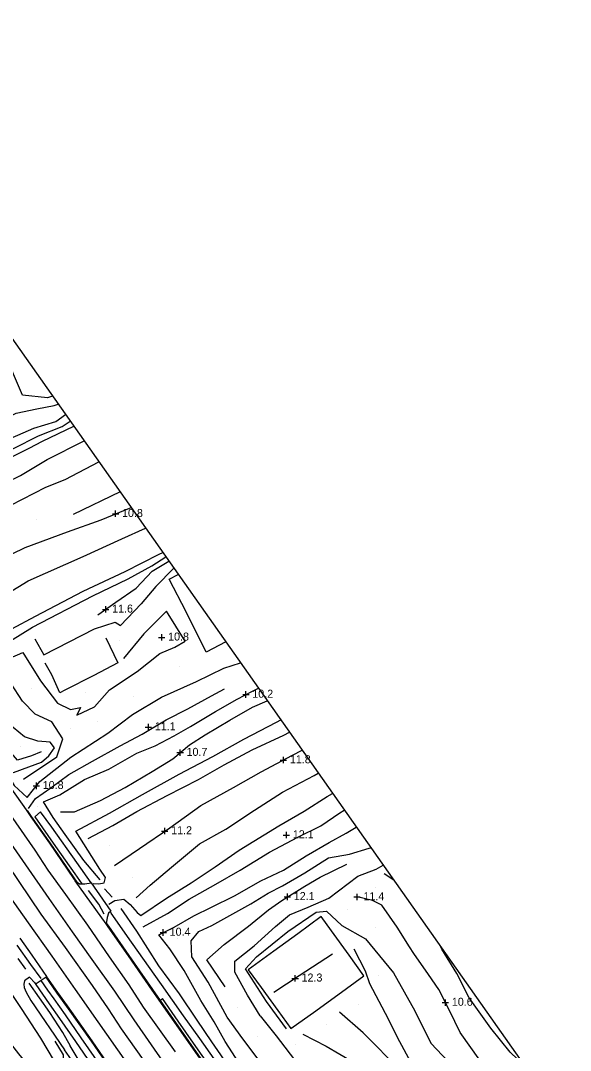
# Model space of a CAD drawing. Extents: x 2316231 to 2323598, y 363169 to 371906.
# Drawn here: x 2319303 to 2319647, y 370026 to 370669 of the extents above; entities that cross this region are included whole.
import ezdxf

# ---------------------------------------------------------------- set-up
doc = ezdxf.new("R2010")
doc.units = 0
for name, color, linetype in [('RD_DTM_BkLn1', 7, 'Continuous'), ('RD_DTM_Spot', 7, 'Continuous'), ('RD_DTM_TinHull', 7, 'Continuous'), ('RD_DTM_Void', 7, 'Continuous'), ('RD_EX_Road', 7, 'Continuous')]:
    doc.layers.add(name, color=color, linetype=linetype)

msp = doc.modelspace()

# ---------------------------------------------------------------- linework, layer by layer
at = {"layer": 'RD_DTM_BkLn1'}
for p, q in [((2319365.212, 370374.913), (2319336.02, 370360.709)), ((2319536.208, 370132.411), (2319530.232, 370136.33)), ((2319355.574, 370126.982), (2319360.216, 370121.89)), ((2319566.359, 370089.293), (2319565.622, 370090.698)), ((2319301.38, 370083.55), (2319306.243, 370076.946))]:
    msp.add_line(p, q, dxfattribs=at)
for points in [[(2319323.059, 370434.692), (2319319.896, 370433.681), (2319304.367, 370435.263), (2319292.639, 370462.632), (2319283.758, 370486.815), (2319280.692, 370494.776)], [(2319065.658, 370482.521), (2319080.069, 370458.772), (2319091.683, 370439.853), (2319104.456, 370419.006), (2319116.05, 370400.96), (2319130.187, 370379.774), (2319143.32, 370359.374), (2319159.232, 370336.203), (2319175.322, 370312.751), (2319186.685, 370296.228), (2319198.804, 370278.012), (2319214.53, 370256.274), (2319229.785, 370234.615), (2319246.848, 370210.512), (2319258.179, 370194.917), (2319272.195, 370174.202), (2319287.562, 370152.554), (2319301.969, 370131.535), (2319315.739, 370111.145), (2319330.93, 370090.281), (2319347.769, 370066.57), (2319357.817, 370052.165), (2319365.977, 370039.641)], [(2319219.832, 370399.897), (2319233.541, 370399.863), (2319245.7, 370401.993), (2319266.565, 370408.678), (2319285.566, 370417.281), (2319300.311, 370424.116), (2319313.209, 370426.77), (2319323.98, 370428.825), (2319326.553, 370429.738)], [(2319311.411, 370414.789), (2319325.164, 370418.884), (2319331.065, 370423.339)], [(2319268.8, 370389.178), (2319280.638, 370393.02), (2319298.644, 370402.063), (2319314.353, 370409.824), (2319328.972, 370415.697), (2319334.09, 370419.048)], [(2319224.804, 370347.018), (2319255.212, 370361.391), (2319276.48, 370372.283), (2319303.023, 370385.042), (2319319.644, 370395.173), (2319342.748, 370406.77)], [(2319205.276, 370329.094), (2319208.399, 370324.8), (2319216.662, 370317.416), (2319220.374, 370329.605), (2319234.482, 370336.956), (2319259.883, 370349.707), (2319277.628, 370356.903), (2319297.046, 370366.659), (2319318.784, 370377.807), (2319330.927, 370382.745), (2319352.052, 370393.576)], [(2319261.18, 370317.641), (2319281.306, 370328.402), (2319305.978, 370340.103), (2319332.312, 370350.031), (2319353.336, 370357.51), (2319372.104, 370365.139)], [(2319244.704, 370329.903), (2319254.201, 370310.183), (2319266.598, 370286.528), (2319281.726, 370303.523), (2319307.817, 370319.316), (2319342.144, 370334.596), (2319366.355, 370345.515), (2319381.191, 370352.251)], [(2319316.013, 370212.534), (2319309.818, 370210.143), (2319301.15, 370207.311), (2319294.878, 370214.612), (2319284.846, 370230.45), (2319269.564, 370250.564), (2319260.042, 370264.7), (2319275.57, 370271.756), (2319296.825, 370281.91), (2319310.588, 370290.504), (2319348.171, 370309.995), (2319370.344, 370320.56), (2319385.014, 370328.783), (2319393.771, 370334.411)], [(2319398.774, 370327.315), (2319387.612, 370315.884), (2319378.352, 370304.929), (2319365.617, 370291.475)], [(2319304.981, 370195.495), (2319325.641, 370209.41), (2319329.406, 370220.659), (2319322.629, 370231.408), (2319312.233, 370236.045), (2319304.319, 370244.312), (2319296.972, 370255.555), (2319291.6, 370269.087), (2319304.427, 370274.55), (2319315.575, 370256.986), (2319326.172, 370243.016), (2319334.376, 370239.078), (2319340.478, 370240.361), (2319338.161, 370235.566), (2319349.174, 370240.608), (2319358.713, 370251.339), (2319375.975, 370262.7), (2319390.171, 370274.069), (2319399.548, 370277.85), (2319405.936, 370281.628), (2319394.265, 370300.368), (2319380.141, 370286.359), (2319367.367, 370270.891)], [(2319312.014, 370283.081), (2319317.607, 370273.241), (2319349.205, 370289.312), (2319362.108, 370293.487), (2319365.617, 370291.475)], [(2319296.566, 370195.807), (2319299.175, 370191.582), (2319307.191, 370184.041), (2319315.117, 370194.094), (2319334.537, 370209.198), (2319357.706, 370224.181), (2319373.1, 370235.894), (2319391.167, 370246.715), (2319412.969, 370256.577), (2319430.022, 370264.793), (2319440.511, 370268.125)], [(2319352.768, 370132.674), (2319342.636, 370144.696), (2319331.038, 370160.895), (2319323.499, 370171.601), (2319317.413, 370181.353), (2319327.618, 370185.647), (2319343.03, 370195.356), (2319358.277, 370201.798), (2319375.67, 370211.659), (2319387.22, 370216.42), (2319398.996, 370222.557), (2319409.318, 370228.463), (2319424.852, 370237.802), (2319438.479, 370245.546), (2319447.948, 370250.48), (2319451.683, 370252.282)], [(2319328.017, 370175.026), (2319336.724, 370175.116), (2319353.125, 370182.137), (2319368.376, 370190.224), (2319385.322, 370200.377), (2319398.211, 370208.302), (2319408.629, 370216.882), (2319418.414, 370223.18), (2319433.78, 370232.341), (2319448.08, 370240.475), (2319457.181, 370244.486)], [(2319345.401, 370158.398), (2319360.73, 370166.663), (2319375.68, 370175.255), (2319394.584, 370185.28), (2319414.171, 370195.258), (2319430.331, 370204.54), (2319447.734, 370213.752), (2319467.621, 370223.058), (2319471.065, 370224.796)], [(2319361.675, 370141.549), (2319377.447, 370152.253), (2319396.247, 370165.21), (2319415.765, 370179.128), (2319436.059, 370190.28), (2319453.351, 370200.085), (2319472.95, 370210.399), (2319478.934, 370213.635)], [(2319375.278, 370121.36), (2319383.949, 370129.385), (2319397.405, 370140.486), (2319414.967, 370155.114), (2319431.239, 370164.318), (2319449.297, 370176.202), (2319466.816, 370187.473), (2319486.583, 370197.888), (2319489.054, 370199.284)], [(2319296.868, 370172.921), (2319312.101, 370151.195), (2319320.217, 370138.63), (2319331.135, 370123.562), (2319344.908, 370104.279), (2319358.501, 370084.606), (2319370.622, 370067.062), (2319379.619, 370053.033), (2319399.706, 370025.294)], [(2319379.699, 370103.298), (2319394.805, 370111.609), (2319408.435, 370120.494), (2319424.998, 370129.932), (2319440.195, 370138.758), (2319458.621, 370149.858), (2319476.293, 370159.36), (2319490.623, 370166.42), (2319502.55, 370174.459), (2319505.336, 370176.193)], [(2319430.871, 370031.671), (2319424.013, 370044.01), (2319415.608, 370057.225), (2319405.269, 370075.962), (2319396.25, 370089.649), (2319389.49, 370098.361), (2319399.025, 370103.116), (2319411.319, 370110.169), (2319422.366, 370115.502), (2319436.787, 370122.707), (2319453.205, 370131.944), (2319467.244, 370138.612), (2319481.568, 370147.53), (2319495.958, 370156.055), (2319506.48, 370161.736), (2319512.793, 370165.618)], [(2319291.539, 370162.974), (2319306.147, 370142.022), (2319320.676, 370120.958), (2319335.296, 370100.129), (2319347.519, 370082.954), (2319361.872, 370063.088), (2319373.932, 370045.125), (2319393.586, 370016.755)], [(2319441.922, 370033.416), (2319432.112, 370046.945), (2319420.359, 370068.673), (2319410.069, 370084.601), (2319409.613, 370094.484), (2319414.507, 370100.425), (2319422.64, 370104.109), (2319446.858, 370117.713), (2319457.83, 370124.21), (2319466.805, 370128.788), (2319480.769, 370136.911), (2319495.408, 370146.287), (2319508.507, 370148.75), (2319520.949, 370152.345), (2319521.979, 370152.591)], [(2319430.894, 370065.793), (2319419.521, 370082.675), (2319430.187, 370092.273), (2319445.469, 370103.717), (2319458.051, 370113.925), (2319466.201, 370119.792), (2319480.727, 370128.764), (2319490.342, 370134.325), (2319506.958, 370142.341)], [(2319452.74, 370047.647), (2319444.791, 370060.667), (2319436.971, 370075.033), (2319437.033, 370081.949), (2319449.121, 370091.521), (2319462.434, 370103.429), (2319471.092, 370110.838), (2319482.675, 370115.632), (2319495.57, 370121.286), (2319513.756, 370135.028), (2319525.203, 370139.241), (2319529.541, 370141.867)], [(2319293.171, 370126.297), (2319307.903, 370105.714), (2319322.602, 370084.986), (2319337.154, 370064.09), (2319351.401, 370043.955)], [(2319355.266, 370111.237), (2319351.913, 370117.389), (2319345.51, 370125.921)], [(2319548.739, 370086.653), (2319546.122, 370090.732), (2319538.252, 370103.017), (2319528.774, 370116.85), (2319523.006, 370119.718), (2319513.309, 370121.935)], [(2319422.55, 370031.381), (2319413.44, 370044.909), (2319402.279, 370061.544), (2319389.531, 370079.023), (2319375.775, 370100.678), (2319365.951, 370114.713)], [(2319469.136, 370039.668), (2319456.633, 370056.62), (2319443.512, 370077.098), (2319450.502, 370084.646), (2319470.069, 370100.287), (2319487.748, 370112.453), (2319494.251, 370113.075), (2319503.73, 370104.087), (2319518.491, 370095.753)], [(2319518.491, 370095.753), (2319536.154, 370074.651), (2319549.373, 370050.767), (2319559.414, 370030.613), (2319570.276, 370019.227), (2319582.845, 370010.006), (2319593.946, 370000.875), (2319605.001, 369992.258), (2319615.528, 369991.916), (2319632.247, 369996.213)], [(2319315.897, 370070.991), (2319309.484, 370079.848), (2319300.886, 370091.888)], [(2319521.267, 370067.639), (2319518.487, 370075.558), (2319511.393, 370089.352)], [(2319617.954, 370016.482), (2319608.994, 370025.028), (2319596.909, 370040.06), (2319583.329, 370059.028), (2319575.614, 370074.145), (2319566.359, 370089.293)], [(2319316.007, 370006.945), (2319302.004, 370023.889), (2319288.639, 370040.832), (2319274.709, 370059.947), (2319264.712, 370076.445), (2319281.91, 370084.325), (2319289.391, 370073.183), (2319303.418, 370052.378), (2319315.514, 370033.771), (2319323.994, 370019.358), (2319330.094, 370019.366), (2319330.003, 370023.372), (2319324.675, 370031.857)], [(2319461.401, 370062.427), (2319477.212, 370072.812), (2319498.042, 370086.49)], [(2319607.296, 370008.564), (2319589.929, 370020.115), (2319577.7, 370037.332), (2319571.04, 370051.071), (2319564.305, 370064.201), (2319557.968, 370073.438), (2319548.739, 370086.653)], [(2319334.242, 370028.742), (2319329.512, 370037.396), (2319321.283, 370049.726), (2319308.482, 370068.212)], [(2319595.617, 369951.088), (2319590.896, 369958.897), (2319583.617, 369970.765), (2319573.419, 369983.615), (2319560.925, 369998.005), (2319552.703, 370009.747), (2319546.83, 370018.861), (2319538.65, 370034.112), (2319532.897, 370045.637), (2319521.267, 370067.639)], [(2319536.662, 370017.101), (2319526.287, 370027.97), (2319517.072, 370037.055), (2319502.362, 370050.048)], [(2319351.401, 370043.955), (2319369.161, 370018.758), (2319385.701, 369995.191), (2319404.266, 369968.558), (2319426.421, 369936.928), (2319449.194, 369904.555), (2319467.594, 369878.424), (2319486.481, 369851.705), (2319503.81, 369826.248), (2319521.512, 369801.076), (2319544.955, 369767.052), (2319558.572, 369748.335), (2319573.687, 369726.172)], [(2319452.74, 370047.647), (2319462.809, 370035.299), (2319476.892, 370016.675), (2319492.475, 369999.428), (2319506.495, 369986.987), (2319515.343, 369978.466), (2319527.005, 369960.38), (2319548.603, 369929.302), (2319571.341, 369897.251), (2319593.12, 369871.186), (2319609.692, 369856.106), (2319630.924, 369866.797)], [(2319365.977, 370039.641), (2319379.673, 370020.195), (2319394.423, 369998.977), (2319409.414, 369978.283), (2319422.541, 369959.39), (2319437.105, 369939.271), (2319454.718, 369913.12), (2319471.543, 369889.277), (2319490.192, 369862.739), (2319509.894, 369834.453), (2319529.502, 369806.441), (2319543.304, 369786.684), (2319559.749, 369763.249), (2319576.32, 369738.823)], [(2319585.177, 369803.165), (2319583.025, 369806.171), (2319567.308, 369827.299), (2319553.329, 369845.325), (2319541.389, 369862.756), (2319527.07, 369881.895), (2319514.836, 369900.366), (2319504.802, 369914.91), (2319491.854, 369933.623), (2319482.234, 369947.556), (2319469.528, 369964.586), (2319457.34, 369982.734), (2319442.09, 370004.098), (2319434.183, 370014.584), (2319422.55, 370031.381)], [(2319520.336, 369904.359), (2319511.244, 369918.66), (2319495.494, 369944.932), (2319475.839, 369970.795), (2319461.207, 369987.035), (2319446.17, 370008.147), (2319430.871, 370031.671)], [(2319601.85, 369840.235), (2319589.342, 369842.891), (2319578.115, 369850.793), (2319562.475, 369870.583), (2319548.776, 369889.635), (2319534.095, 369908.059), (2319518.222, 369929.08), (2319506.767, 369948.096), (2319496.902, 369960.646), (2319482.239, 369977.972), (2319473.613, 369990.133), (2319456.598, 370013.989), (2319441.922, 370033.416)], [(2319479.478, 370036.274), (2319493.943, 370028.844), (2319511.115, 370018.811), (2319526.462, 370011.317), (2319537.155, 370001.735), (2319549.094, 369986.286), (2319564.493, 369963.787), (2319576.661, 369946.403), (2319585.076, 369930.399), (2319596.399, 369918.271), (2319607.875, 369921.902)], [(2319339.598, 370019.618), (2319334.109, 370028.97)]]:
    msp.add_lwpolyline(points, dxfattribs=at)
at = {"layer": 'RD_DTM_Spot'}
for p, q in [((2319312.871, 370357.913), (2319312.871, 370357.913)), ((2319364.833, 370282.088), (2319364.833, 370282.088)), ((2319391.27, 370284.059), (2319391.27, 370284.059)), ((2319402.114, 370265.836), (2319402.114, 370265.836)), ((2319309.71, 370252.054), (2319309.71, 370252.054)), ((2319343.466, 370249.43), (2319343.466, 370249.43)), ((2319373.711, 370247.43), (2319373.711, 370247.43)), ((2319351.322, 370231.248), (2319351.322, 370231.248)), ((2319334.492, 370227.149), (2319334.492, 370227.149)), ((2319303.331, 370216.091), (2319303.331, 370216.091)), ((2319313.757, 370178.273), (2319313.757, 370178.273)), ((2319358.483, 370153.799), (2319358.483, 370153.799)), ((2319372.781, 370134.392), (2319372.781, 370134.392)), ((2319524.626, 370127.76), (2319524.626, 370127.76)), ((2319507.537, 370114.116), (2319507.537, 370114.116)), ((2319524.799, 370102.636), (2319524.799, 370102.636)), ((2319400.82, 370095.781), (2319400.82, 370095.781)), ((2319526.703, 370073.065), (2319526.703, 370073.065)), ((2319438.505, 370052.636), (2319438.505, 370052.636)), ((2319514.313, 370054.915), (2319514.313, 370054.915)), ((2319494.061, 370042.249), (2319494.061, 370042.249)), ((2319450.928, 370035.058), (2319450.928, 370035.058)), ((2319474.896, 370029.649), (2319474.896, 370029.649))]:
    msp.add_line(p, q, dxfattribs=at)
at = {"layer": 'RD_DTM_TinHull'}
msp.add_lwpolyline([(2319170.205, 370651.465), (2319634.1, 369993.584), (2319863.396, 370037.401), (2320246.301, 369984.488), (2320646.583, 370063.477), (2321009.446, 370233.043), (2320870.667, 370593.666), (2320743.045, 370821.597), (2320657.552, 371017.902), (2320535.413, 371221.514), (2319782.271, 371232.132)], dxfattribs=at)
at = {"layer": 'RD_DTM_Void'}
for p, q in [((2319360.483, 370361.228), (2319364.483, 370361.228)), ((2319362.483, 370359.228), (2319362.483, 370363.228)), ((2319354.29, 370301.531), (2319358.29, 370301.531)), ((2319356.29, 370299.531), (2319356.29, 370303.531)), ((2319389.27, 370284.059), (2319393.27, 370284.059)), ((2319391.27, 370282.059), (2319391.27, 370286.059)), ((2319443.874, 370246.357), (2319443.874, 370250.357)), ((2319441.874, 370248.357), (2319445.874, 370248.357)), ((2319382.951, 370226.047), (2319382.951, 370230.047)), ((2319380.951, 370228.047), (2319384.951, 370228.047)), ((2319400.781, 370212.065), (2319404.781, 370212.065)), ((2319402.781, 370210.065), (2319402.781, 370214.065)), ((2319465.321, 370207.437), (2319469.321, 370207.437)), ((2319467.321, 370205.437), (2319467.321, 370209.437)), ((2319310.946, 370191.341), (2319314.946, 370191.341)), ((2319312.946, 370189.341), (2319312.946, 370193.341)), ((2319391.185, 370163.1), (2319395.185, 370163.1)), ((2319393.185, 370161.1), (2319393.185, 370165.1)), ((2319467.189, 370160.598), (2319471.189, 370160.598)), ((2319469.189, 370158.598), (2319469.189, 370162.598)), ((2319467.779, 370122.002), (2319471.779, 370122.002)), ((2319469.779, 370120.002), (2319469.779, 370124.002)), ((2319511.309, 370121.935), (2319515.309, 370121.935)), ((2319513.309, 370119.935), (2319513.309, 370123.935)), ((2319392.235, 370097.73), (2319392.235, 370101.73)), ((2319390.235, 370099.73), (2319394.235, 370099.73)), ((2319472.633, 370071.119), (2319476.633, 370071.119)), ((2319474.633, 370069.119), (2319474.633, 370073.119)), ((2319568.519, 370053.987), (2319568.519, 370057.987)), ((2319566.519, 370055.987), (2319570.519, 370055.987))]:
    msp.add_line(p, q, dxfattribs=at)
at = {"layer": 'RD_EX_Road'}
for p, q in [((2319356.463, 370105.224), (2319337.281, 370132.006)), ((2319319.574, 370072.111), (2319319.158, 370071.833))]:
    msp.add_line(p, q, dxfattribs=at)
for points in [[(2319197.202, 370399.035), (2319202.677, 370395.452), (2319214.347, 370390.141), (2319227.625, 370388.127), (2319240.539, 370387.591), (2319253.347, 370389.809), (2319268.113, 370396.509), (2319285.062, 370403.551), (2319301.418, 370410.326), (2319311.411, 370414.789)], [(2319198.924, 370329.498), (2319204.177, 370332.622), (2319221.748, 370341.934), (2319214.201, 370353.938), (2319237.183, 370365.665), (2319263.717, 370379.432), (2319288.773, 370392.474), (2319308.359, 370402.229), (2319316.807, 370406.584), (2319336.333, 370415.868)], [(2319234.586, 370324.914), (2319243.193, 370311.867), (2319233.091, 370304.17), (2319246.986, 370284.305), (2319259.483, 370269.659), (2319278.107, 370279.427), (2319297.705, 370289.35), (2319312.485, 370297.236), (2319342.236, 370312.886), (2319368.487, 370325.22), (2319389.62, 370336.034), (2319391.869, 370337.109)], [(2319351.309, 370298.035), (2319362.654, 370305.997), (2319375.254, 370314.684), (2319385.274, 370325.335), (2319395.684, 370331.698)], [(2319431.236, 370281.279), (2319419.08, 370274.847), (2319406.518, 370299.902), (2319395.949, 370320.43), (2319401.636, 370323.257)], [(2319356.264, 370283.699), (2319363.936, 370268.079), (2319348.921, 370260.328), (2319330.825, 370251.106), (2319327.642, 370249.368), (2319322.645, 370260.65), (2319318.411, 370268.013)], [(2319293.219, 370199.9), (2319298.635, 370199.641), (2319308.313, 370203.119), (2319316.266, 370206.132), (2319320.718, 370210.128), (2319324.222, 370215.088), (2319321.612, 370218.619), (2319313.97, 370219.187), (2319305.618, 370221.972), (2319298.548, 370227.719), (2319292.735, 370239.383), (2319284.701, 370253.358), (2319281.4, 370257.899)], [(2319308.125, 370177.235), (2319312.449, 370183.514), (2319321.967, 370190.104), (2319333.29, 370198.391), (2319348.094, 370206.792), (2319365.352, 370216.396), (2319378.978, 370223.569), (2319393.952, 370232.507), (2319407.588, 370239.445), (2319422.448, 370247.611), (2319430.438, 370251.956)], [(2319348.453, 370130.368), (2319351.978, 370130.225), (2319355.382, 370130.821), (2319356.084, 370134.132), (2319352.515, 370139.21), (2319337.645, 370163.028), (2319358.612, 370174.357), (2319379.232, 370186.012), (2319402.071, 370198.701), (2319423.171, 370209.639), (2319442.491, 370220.435), (2319462.896, 370231.094), (2319465.656, 370232.466)], [(2319289.614, 370200.805), (2319297.111, 370189.807), (2319306.555, 370176.254)], [(2319358.18, 370117.396), (2319361.968, 370119.681), (2319367.532, 370120.473), (2319371.642, 370117.172), (2319375.927, 370112.316), (2319378.261, 370110.307), (2319394.247, 370121.246), (2319409.747, 370130.731), (2319424.622, 370140.688), (2319439.577, 370151.181), (2319464.47, 370166.462), (2319480.35, 370175.588), (2319494.641, 370184.685), (2319497.994, 370186.605)], [(2319306.555, 370176.254), (2319309.578, 370171.916), (2319321.232, 370155.447), (2319336.196, 370133.521), (2319337.281, 370132.006)], [(2319338.466, 370131.209), (2319336.606, 370133.807), (2319321.643, 370155.733), (2319309.987, 370172.203), (2319307.315, 370176.038)], [(2319347.145, 370130.718), (2319338.202, 370143.554), (2319322.723, 370165.493), (2319315.629, 370175.18), (2319312.029, 370171.999), (2319324.909, 370153.413), (2319336.897, 370136.395), (2319341.422, 370130.167)], [(2319337.281, 370132.006), (2319339.937, 370130.221), (2319341.422, 370130.167)], [(2319341.422, 370130.167), (2319343.204, 370130.101), (2319347.145, 370130.718), (2319359.467, 370113.073), (2319359.331, 370112.957)], [(2319359.331, 370112.957), (2319358.043, 370111.857), (2319357.275, 370109.094), (2319356.463, 370105.224)], [(2319415.076, 370033.481), (2319404.83, 370047.796), (2319391.125, 370067.246), (2319372.39, 370093.804), (2319359.721, 370111.797), (2319359.331, 370112.957)], [(2319490.966, 370109.696), (2319476.382, 370098.899), (2319461.344, 370088.032), (2319445.228, 370076.419), (2319453.43, 370065.298), (2319463.728, 370050.979), (2319471.929, 370039.763), (2319487.47, 370050.902), (2319506.654, 370064.839), (2319517.558, 370072.731), (2319508.386, 370085.552), (2319497.353, 370100.806), (2319490.966, 370109.696)], [(2319426.173, 370005.399), (2319407.833, 370031.661), (2319385.287, 370063.83), (2319370.555, 370085.124), (2319357.82, 370103.33), (2319356.463, 370105.224)], [(2319568.162, 369803.154), (2319556.113, 369820.81), (2319541.996, 369839.888), (2319527.855, 369860.393), (2319511.067, 369884.391), (2319492.799, 369910.868), (2319477.229, 369933.012), (2319457.515, 369960.914), (2319441.086, 369984.861), (2319426.583, 370005.685), (2319408.243, 370031.948), (2319385.697, 370064.116), (2319370.966, 370085.41), (2319358.228, 370103.619), (2319356.87, 370105.515)], [(2319319.574, 370072.111), (2319319.448, 370072.292), (2319310.394, 370085.654), (2319302.872, 370096.133)], [(2319312.284, 370068.148), (2319308.726, 370071.792), (2319305.519, 370069.472), (2319305.056, 370067.549), (2319305.285, 370065.377), (2319306.666, 370062.554), (2319309.451, 370057.231), (2319330.586, 370026.446)], [(2319319.158, 370071.833), (2319312.822, 370067.597), (2319312.284, 370068.148)], [(2319551.457, 369733.671), (2319538.944, 369751.354), (2319523.766, 369772.508), (2319512.164, 369789.667), (2319496.302, 369812.216), (2319480.485, 369834.873), (2319465.992, 369855.411), (2319449.048, 369879.567), (2319427.799, 369909.523), (2319414.234, 369929.352), (2319397.374, 369952.978), (2319382.263, 369975.219), (2319367.216, 369996.562), (2319353.845, 370015.484), (2319341.032, 370034.022), (2319331.081, 370048.399), (2319324.102, 370058.235), (2319320.199, 370063.729), (2319315.96, 370069.694)], [(2319513.446, 369794.62), (2319502.66, 369809.935), (2319489.912, 369828.349), (2319475.459, 369849.038), (2319459.997, 369870.82), (2319439.829, 369899.386), (2319424.24, 369921.943), (2319410.092, 369941.69), (2319393.635, 369965.448), (2319376.633, 369989.519), (2319363.422, 370008.571), (2319347.419, 370031.882), (2319332.066, 370053.564), (2319326.043, 370061.936), (2319319.158, 370071.833)], [(2319547.26, 369746.771), (2319534.463, 369764.707), (2319514.918, 369793.399), (2319503.069, 369810.221), (2319490.322, 369828.635), (2319475.868, 369849.326), (2319460.405, 369871.108), (2319440.239, 369899.672), (2319424.649, 369922.231), (2319410.5, 369941.978), (2319394.045, 369965.735), (2319377.043, 369989.806), (2319363.833, 370008.855), (2319347.829, 370032.168), (2319332.473, 370053.855), (2319326.451, 370062.225), (2319319.574, 370072.111)], [(2319552.06, 369725.516), (2319535.509, 369748.906), (2319520.304, 369770.097), (2319508.691, 369787.271), (2319492.847, 369809.795), (2319477.032, 369832.45), (2319462.542, 369852.984), (2319445.601, 369877.136), (2319424.337, 369907.112), (2319410.776, 369926.936), (2319393.912, 369950.567), (2319378.794, 369972.818), (2319363.77, 369994.129), (2319350.387, 370013.068), (2319337.563, 370031.622), (2319327.612, 370045.998), (2319321.084, 370055.244), (2319312.878, 370067.317), (2319312.284, 370068.148)], [(2319411.123, 370030.693), (2319401.543, 370044.323), (2319391.819, 370058.56), (2319390.424, 370057.372)], [(2319570.995, 369802.831), (2319553.859, 369826.503), (2319536.682, 369850.946), (2319517.852, 369877.68), (2319501.136, 369901.689), (2319482.981, 369927.429), (2319461.193, 369958.988), (2319443.228, 369984.597), (2319431.408, 370001.929), (2319411.123, 370030.693)], [(2319787.95, 369483.364), (2319765.651, 369521.489), (2319743.921, 369555.334), (2319724.619, 369586.553), (2319703.742, 369618.454), (2319683.639, 369648.938), (2319666.916, 369673.314), (2319654.152, 369693.961), (2319637.209, 369717.522), (2319619.664, 369742.991), (2319602.386, 369766.283), (2319589.715, 369785.039), (2319578.115, 369801.246), (2319557.797, 369829.313), (2319540.638, 369853.73), (2319521.815, 369880.455), (2319505.098, 369904.466), (2319486.949, 369930.198), (2319465.165, 369961.751), (2319447.207, 369987.349), (2319435.384, 370004.687), (2319415.076, 370033.481)], [(2319325.09, 370009.524), (2319336.343, 370018.059), (2319330.586, 370026.446)]]:
    msp.add_lwpolyline(points, dxfattribs=at)

# ---------------------------------------------------------------- texts
at = {"layer": 'RD_DTM_Void'}
for s, p in [('10.8', (2319366.483, 370359.228)), ('11.6', (2319360.29, 370299.531)), ('10.8', (2319395.27, 370282.059)), ('10.2', (2319447.874, 370246.357)), ('11.1', (2319386.951, 370226.047)), ('10.7', (2319406.781, 370210.065)), ('11.8', (2319471.321, 370205.437)), ('10.8', (2319316.946, 370189.341)), ('11.2', (2319397.185, 370161.1)), ('12.1', (2319473.189, 370158.598)), ('12.1', (2319473.779, 370120.002)), ('11.4', (2319517.309, 370119.935)), ('10.4', (2319396.235, 370097.73)), ('12.3', (2319478.633, 370069.119)), ('10.6', (2319572.519, 370053.987))]:
    msp.add_text(s, height=5, dxfattribs=at).set_placement(p)

doc.saveas('drawing.dxf')
